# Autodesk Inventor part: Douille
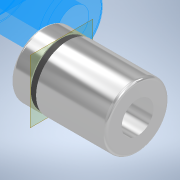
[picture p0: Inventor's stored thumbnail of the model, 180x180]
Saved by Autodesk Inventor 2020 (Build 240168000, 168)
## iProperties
Created: 2023-10
Part Number: Douille
Material: Aluminium 6061
Document SubType Name: Modeling
Designer: bruno
Density: 2.7 g/cm^3
Appearance: Aluminium - Plat
Mass: 2.36073 g
Surface Area: 8.21619 cm^2
Volume: 0.874343 cm^3
Author: bruno
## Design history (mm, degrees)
sketch "Esquisse1"
  geometry: C1 r 5 at (0, 0); C2 r 2.5 at (0, 0); 1 further point
  constraints: 2 centre point, 2 coincident
  dimensions: "d0" = 10 diameter of C1; "d1" = 5 diameter of C2
extrude "Extrusion1" new body sketch "Esquisse1" distance "d2" = 15; taper "d3" = 0 deg
fillet "Congé1" dims "d4" = 0.5
node "Plan de construction1"
sketch "Esquisse2"
  geometry: C1 r 5 at (0, 0) reference; C2 r 4.807 at (0, 0); 1 further point
  constraints: 1 centre point, 1 coincident
extrude "Extrusion2" cut sketch "Esquisse2" distance "d6" = 1; taper "d7" = 0 deg
node "Solide1"
other parameters: "d5" = -2.5
